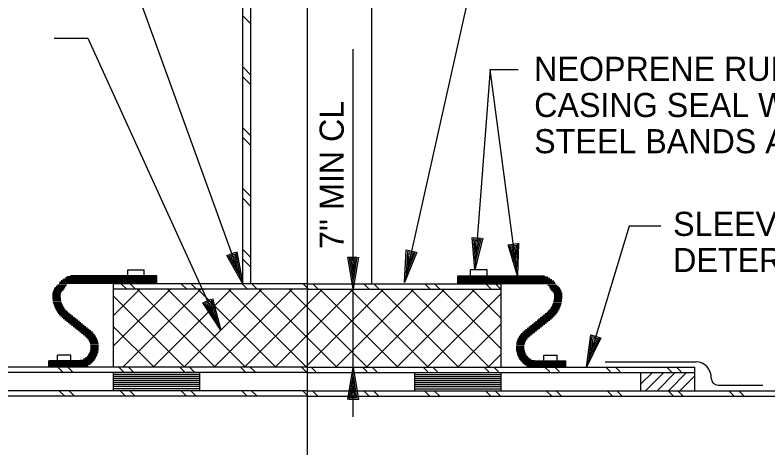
# Model space of a CAD drawing. Extents: x 22422.9 to 22498.9, y 22369.6 to 22415.
# Drawn here: x 22465.87 to 22471.7, y 22388.07 to 22391.43 of the extents above; entities that cross this region are included whole.
import ezdxf

# ---------------------------------------------------------------- set-up
doc = ezdxf.new("R2010")
doc.units = 0
for name, color, linetype in [('Level 1', 7, 'Continuous'), ('Level 2', 7, 'Continuous'), ('Level 4', 7, 'Continuous'), ('Level 7', 7, 'Continuous'), ('Level 8', 7, 'Continuous')]:
    doc.layers.add(name, color=color, linetype=linetype)

msp = doc.modelspace()

# ---------------------------------------------------------------- linework, layer by layer
at = {"layer": 'Level 1'}
for p, q in [((22468.1298, 22384.5979), (22468.1298, 22394.0328)), ((22468.4836, 22389.3005), (22468.4836, 22391.1625)), ((22469.7308, 22389.6069), (22469.7308, 22389.6069)), ((22467.6062, 22389.5324), (22467.6062, 22389.5324)), ((22469.7393, 22389.5424), (22469.7393, 22389.5424)), ((22469.7399, 22389.5381), (22469.7399, 22389.5381)), ((22469.7399, 22389.5381), (22469.7399, 22389.5381)), ((22466.7386, 22389.4038), (22466.7386, 22389.4515)), ((22466.7386, 22389.4515), (22466.866, 22389.4515)), ((22466.866, 22389.4038), (22466.866, 22389.4515)), ((22467.6298, 22389.4672), (22467.6298, 22389.4672)), ((22469.3936, 22389.4038), (22469.3936, 22389.4515)), ((22469.521, 22389.4515), (22469.3936, 22389.4515)), ((22469.521, 22389.4038), (22469.521, 22389.4515)), ((22466.6298, 22388.6963), (22466.6298, 22389.3422)), ((22468.1298, 22389.3422), (22466.6298, 22389.3422)), ((22468.1298, 22389.3422), (22469.6298, 22389.3422)), ((22469.6298, 22388.6963), (22469.6298, 22389.3422)), ((22468.1298, 22389.3005), (22466.6298, 22389.3005)), ((22468.1298, 22389.3005), (22469.6298, 22389.3005)), ((22468.4836, 22388.6963), (22468.4836, 22389.3005)), ((22466.999, 22389.0152), (22466.999, 22389.0152)), ((22467.0402, 22388.9594), (22467.0402, 22388.9594)), ((22468.5915, 22388.8065), (22468.5915, 22388.8065)), ((22466.1946, 22388.746), (22466.1946, 22388.789)), ((22466.2982, 22388.789), (22466.1946, 22388.789)), ((22466.2982, 22388.746), (22466.2982, 22388.789)), ((22469.9614, 22388.746), (22469.9614, 22388.789)), ((22469.9614, 22388.789), (22470.065, 22388.789)), ((22470.065, 22388.746), (22470.065, 22388.789)), ((22468.1298, 22388.6963), (22465.1298, 22388.6963)), ((22468.1298, 22388.6963), (22471.1298, 22388.6963)), ((22468.4836, 22388.3111), (22468.4836, 22388.6963)), ((22468.581, 22388.738), (22468.581, 22388.738)), ((22468.1298, 22388.6547), (22465.1298, 22388.6547)), ((22467.2965, 22388.639), (22466.6298, 22388.639)), ((22468.1298, 22388.6547), (22471.1298, 22388.6547)), ((22468.9631, 22388.639), (22469.6298, 22388.639)), ((22470.7131, 22388.5663), (22470.8015, 22388.6547)), ((22470.7493, 22388.514), (22470.8899, 22388.6547)), ((22470.8377, 22388.514), (22470.9783, 22388.6547)), ((22470.9261, 22388.514), (22471.0667, 22388.6547)), ((22471.0145, 22388.514), (22471.1298, 22388.6294)), ((22467.2965, 22388.6234), (22466.6298, 22388.6234)), ((22467.2965, 22388.6078), (22466.6298, 22388.6078)), ((22467.2965, 22388.5922), (22466.6298, 22388.5922)), ((22467.2965, 22388.5765), (22466.6298, 22388.5765)), ((22468.9631, 22388.6234), (22469.6298, 22388.6234)), ((22468.9631, 22388.6078), (22469.6298, 22388.6078)), ((22468.9631, 22388.5922), (22469.6298, 22388.5922)), ((22468.9631, 22388.5765), (22469.6298, 22388.5765)), ((22467.2965, 22388.5609), (22466.6298, 22388.5609)), ((22467.2965, 22388.5453), (22466.6298, 22388.5453)), ((22467.2965, 22388.5297), (22466.6298, 22388.5297)), ((22468.9631, 22388.5609), (22469.6298, 22388.5609)), ((22468.9631, 22388.5453), (22469.6298, 22388.5453)), ((22468.9631, 22388.5297), (22469.6298, 22388.5297))]:
    msp.add_line(p, q, dxfattribs=at)
msp.add_lwpolyline([(22469.7404, 22389.5539), (22469.7399, 22389.5381), (22469.7353, 22389.5532), (22469.7397, 22389.5538), (22469.7393, 22389.5424), (22469.7362, 22389.5527), (22469.739, 22389.5531), (22469.7388, 22389.5466), (22469.7371, 22389.5521), (22469.7383, 22389.5523), (22469.7382, 22389.5508)], dxfattribs=at)
at = {"layer": 'Level 2'}
for p, q in [((22467.6298, 22389.3422), (22467.6298, 22393.2738)), ((22467.6923, 22389.3422), (22467.6923, 22393.2738)), ((22468.6298, 22389.3422), (22468.6298, 22393.2738)), ((22467.6298, 22389.3422), (22466.68, 22391.9696)), ((22469.7577, 22389.4038), (22469.5456, 22391.0035)), ((22469.5456, 22391.0035), (22469.7633, 22391.0035)), ((22466.9643, 22389.4038), (22466.2958, 22389.4038)), ((22466.9643, 22389.3422), (22466.9643, 22389.4038)), ((22469.2953, 22389.4038), (22469.9648, 22389.4038)), ((22469.2953, 22389.3422), (22469.2953, 22389.4038)), ((22466.3909, 22388.746), (22466.1285, 22388.746)), ((22466.1285, 22388.6963), (22466.1285, 22388.746)), ((22469.8687, 22388.746), (22470.1311, 22388.746)), ((22470.1311, 22388.6963), (22470.1311, 22388.746)), ((22471.1298, 22388.514), (22471.1298, 22388.6963)), ((22466.6298, 22388.514), (22466.6298, 22388.6547)), ((22467.2965, 22388.514), (22467.2965, 22388.6547)), ((22468.9631, 22388.514), (22468.9631, 22388.6547)), ((22469.6298, 22388.514), (22469.6298, 22388.6547)), ((22470.7131, 22388.514), (22470.7131, 22388.6547)), ((22468.1298, 22388.514), (22461.4631, 22388.514)), ((22468.1298, 22388.514), (22474.774, 22388.514)), ((22468.1298, 22388.4724), (22461.4924, 22388.4724)), ((22468.1298, 22388.4724), (22474.7645, 22388.4724))]:
    msp.add_line(p, q, dxfattribs=at)
for points in [[(22469.7546, 22391.9303), (22469.458, 22391.9303), (22468.8819, 22389.353)], [(22466.1686, 22391.2463), (22466.4291, 22391.2463), (22467.4606, 22388.9844)], [(22469.5456, 22391.0035), (22469.4274, 22389.4506)], [(22470.867, 22389.79), (22470.6212, 22389.79), (22470.2916, 22388.6963)], [(22469.4875, 22389.6961), (22469.4274, 22389.4506), (22469.4051, 22389.7024), (22469.4756, 22389.697), (22469.4327, 22389.5197), (22469.4176, 22389.6907), (22469.4628, 22389.6873), (22469.4377, 22389.5862), (22469.4301, 22389.6791), (22469.4487, 22389.6776), (22469.443, 22389.6553)], [(22469.7659, 22389.6564), (22469.7577, 22389.4038), (22469.684, 22389.6455), (22469.754, 22389.6548), (22469.7486, 22389.4725), (22469.6986, 22389.6367), (22469.7435, 22389.6427), (22469.7398, 22389.5386), (22469.7132, 22389.6279), (22469.7317, 22389.6304), (22469.7307, 22389.6074)], [(22467.5839, 22389.5907), (22467.6298, 22389.3422), (22467.5062, 22389.5626), (22467.5726, 22389.5866), (22467.6062, 22389.4074), (22467.5223, 22389.5571), (22467.565, 22389.5725), (22467.5836, 22389.4701), (22467.5385, 22389.5516), (22467.5561, 22389.5579), (22467.56, 22389.5353)], [(22468.9766, 22389.5873), (22468.8819, 22389.353), (22468.8959, 22389.6053), (22468.9649, 22389.5899), (22468.897, 22389.4207), (22468.9066, 22389.592), (22468.9508, 22389.5821), (22468.9115, 22389.4857), (22468.9173, 22389.5787), (22468.9355, 22389.5746), (22468.9267, 22389.5534)], [(22468.5249, 22389.5498), (22468.4836, 22389.3005), (22468.4422, 22389.5498), (22468.5129, 22389.5498), (22468.4836, 22389.3698), (22468.4556, 22389.5392), (22468.5009, 22389.5392), (22468.4836, 22389.4365), (22468.4689, 22389.5285), (22468.4876, 22389.5285), (22468.4836, 22389.5058)], [(22466.9631, 22389.3964), (22466.2686, 22389.3964)], [(22469.2965, 22389.3964), (22469.991, 22389.3964)], [(22466.2672, 22389.3317), (22466.195, 22389.3317)], [(22466.9631, 22389.3444), (22466.2073, 22389.3444)], [(22466.9631, 22389.3548), (22466.2137, 22389.3548)], [(22466.9631, 22389.3652), (22466.2223, 22389.3652)], [(22466.9631, 22389.3756), (22466.2375, 22389.3756)], [(22466.9631, 22389.386), (22466.2533, 22389.386)], [(22469.2965, 22389.386), (22470.0063, 22389.386)], [(22469.2965, 22389.3756), (22470.0221, 22389.3756)], [(22469.2965, 22389.3652), (22470.0373, 22389.3652)], [(22469.2965, 22389.3548), (22470.0459, 22389.3548)], [(22469.2965, 22389.3444), (22470.0524, 22389.3444)], [(22469.9924, 22389.3317), (22470.0646, 22389.3317)], [(22466.2292, 22389.2797), (22466.1608, 22389.2797)], [(22466.2389, 22389.2901), (22466.1634, 22389.2901)], [(22466.246, 22389.3005), (22466.1692, 22389.3005)], [(22466.2524, 22389.3109), (22466.1757, 22389.3109)], [(22466.2582, 22389.3213), (22466.1847, 22389.3213)], [(22470.0014, 22389.3213), (22470.0749, 22389.3213)], [(22470.0072, 22389.3109), (22470.084, 22389.3109)], [(22470.0137, 22389.3005), (22470.0904, 22389.3005)], [(22470.0207, 22389.2901), (22470.0962, 22389.2901)], [(22470.0304, 22389.2797), (22470.0988, 22389.2797)], [(22466.2185, 22389.2484), (22466.156, 22389.2484)], [(22466.2189, 22389.2588), (22466.1563, 22389.2588)], [(22466.2189, 22389.238), (22466.1563, 22389.238)], [(22466.222, 22389.2692), (22466.157, 22389.2692)], [(22466.2199, 22389.2276), (22466.157, 22389.2276)], [(22466.2215, 22389.2172), (22466.1582, 22389.2172)], [(22467.3947, 22389.2284), (22467.4606, 22388.9844), (22467.3195, 22389.1941), (22467.3838, 22389.2235), (22467.4318, 22389.0475), (22467.3361, 22389.19), (22467.3773, 22389.2088), (22467.4042, 22389.1082), (22467.3527, 22389.1858), (22467.3696, 22389.1935), (22467.3754, 22389.1713)], [(22470.0376, 22389.2692), (22470.1026, 22389.2692)], [(22470.0381, 22389.2172), (22470.1014, 22389.2172)], [(22470.0398, 22389.2276), (22470.1026, 22389.2276)], [(22470.0407, 22389.2588), (22470.1033, 22389.2588)], [(22470.0407, 22389.238), (22470.1033, 22389.238)], [(22470.0411, 22389.2484), (22470.1036, 22389.2484)], [(22466.2239, 22389.2067), (22466.1599, 22389.2067)], [(22466.2269, 22389.1963), (22466.1621, 22389.1963)], [(22466.2307, 22389.1859), (22466.1648, 22389.1859)], [(22466.2354, 22389.1755), (22466.168, 22389.1755)], [(22466.2409, 22389.1651), (22466.1718, 22389.1651)], [(22466.2475, 22389.1547), (22466.1761, 22389.1547)], [(22470.0121, 22389.1547), (22470.0835, 22389.1547)], [(22470.0187, 22389.1651), (22470.0878, 22389.1651)], [(22470.0242, 22389.1755), (22470.0916, 22389.1755)], [(22470.0289, 22389.1859), (22470.0949, 22389.1859)], [(22470.0327, 22389.1963), (22470.0975, 22389.1963)], [(22470.0357, 22389.2067), (22470.0997, 22389.2067)], [(22466.2552, 22389.1442), (22466.1811, 22389.1442)], [(22466.2643, 22389.1338), (22466.1868, 22389.1338)], [(22466.2751, 22389.1234), (22466.1932, 22389.1234)], [(22466.2877, 22389.113), (22466.2004, 22389.113)], [(22466.3004, 22389.1026), (22466.2085, 22389.1026)], [(22469.9592, 22389.1026), (22470.0511, 22389.1026)], [(22469.972, 22389.113), (22470.0592, 22389.113)], [(22469.9845, 22389.1234), (22470.0664, 22389.1234)], [(22469.9953, 22389.1338), (22470.0728, 22389.1338)], [(22470.0044, 22389.1442), (22470.0785, 22389.1442)], [(22466.3132, 22389.0922), (22466.2176, 22389.0922)], [(22466.3259, 22389.0817), (22466.228, 22389.0817)], [(22466.3387, 22389.0713), (22466.2399, 22389.0713)], [(22466.3515, 22389.0609), (22466.2526, 22389.0609)], [(22466.3642, 22389.0505), (22466.2654, 22389.0505)], [(22466.377, 22389.0401), (22466.2782, 22389.0401)], [(22469.8826, 22389.0401), (22469.9815, 22389.0401)], [(22469.8954, 22389.0505), (22469.9942, 22389.0505)], [(22469.9081, 22389.0609), (22470.007, 22389.0609)], [(22469.9209, 22389.0713), (22470.0197, 22389.0713)], [(22469.9337, 22389.0817), (22470.0316, 22389.0817)], [(22469.9464, 22389.0922), (22470.042, 22389.0922)], [(22466.3898, 22389.0297), (22466.2909, 22389.0297)], [(22466.4025, 22389.0192), (22466.3037, 22389.0192)], [(22466.4153, 22389.0088), (22466.3165, 22389.0088)], [(22466.4281, 22388.9984), (22466.3292, 22388.9984)], [(22466.4408, 22388.988), (22466.342, 22388.988)], [(22469.8188, 22388.988), (22469.9176, 22388.988)], [(22469.8315, 22388.9984), (22469.9304, 22388.9984)], [(22469.8443, 22389.0088), (22469.9432, 22389.0088)], [(22469.8571, 22389.0192), (22469.9559, 22389.0192)], [(22469.8698, 22389.0297), (22469.9687, 22389.0297)], [(22466.4536, 22388.9776), (22466.3548, 22388.9776)], [(22466.4649, 22388.9672), (22466.3675, 22388.9672)], [(22466.4744, 22388.9567), (22466.3803, 22388.9567)], [(22466.4825, 22388.9463), (22466.393, 22388.9463)], [(22466.4893, 22388.9359), (22466.4058, 22388.9359)], [(22466.4951, 22388.9255), (22466.4182, 22388.9255)], [(22469.7645, 22388.9255), (22469.8414, 22388.9255)], [(22469.7703, 22388.9359), (22469.8538, 22388.9359)], [(22469.7772, 22388.9463), (22469.8666, 22388.9463)], [(22469.7852, 22388.9567), (22469.8793, 22388.9567)], [(22469.7947, 22388.9672), (22469.8921, 22388.9672)], [(22469.806, 22388.9776), (22469.9049, 22388.9776)], [(22470.4031, 22388.9231), (22470.2916, 22388.6963), (22470.3239, 22388.947), (22470.3916, 22388.9266), (22470.3116, 22388.7627), (22470.3336, 22388.9329), (22470.377, 22388.9198), (22470.3308, 22388.8265), (22470.3433, 22388.9189), (22470.3612, 22388.9135), (22470.3508, 22388.8929)], [(22466.5, 22388.9151), (22466.4278, 22388.9151)], [(22466.504, 22388.9047), (22466.4352, 22388.9047)], [(22466.5072, 22388.8942), (22466.4408, 22388.8942)], [(22466.5098, 22388.8838), (22466.4451, 22388.8838)], [(22466.5116, 22388.8734), (22466.4481, 22388.8734)], [(22466.5128, 22388.863), (22466.45, 22388.863)], [(22469.7468, 22388.863), (22469.8096, 22388.863)], [(22469.748, 22388.8734), (22469.8115, 22388.8734)], [(22469.7498, 22388.8838), (22469.8145, 22388.8838)], [(22469.7524, 22388.8942), (22469.8188, 22388.8942)], [(22469.7556, 22388.9047), (22469.8244, 22388.9047)], [(22469.7597, 22388.9151), (22469.8318, 22388.9151)], [(22466.5087, 22388.8109), (22466.4433, 22388.8109)], [(22466.5108, 22388.8213), (22466.4469, 22388.8213)], [(22466.5123, 22388.8317), (22466.4493, 22388.8317)], [(22466.5131, 22388.8422), (22466.4505, 22388.8422)], [(22466.5133, 22388.8526), (22466.4508, 22388.8526)], [(22469.7463, 22388.8526), (22469.8088, 22388.8526)], [(22469.7465, 22388.8422), (22469.8091, 22388.8422)], [(22469.7473, 22388.8317), (22469.8104, 22388.8317)], [(22469.7488, 22388.8213), (22469.8127, 22388.8213)], [(22469.7509, 22388.8109), (22469.8163, 22388.8109)], [(22466.4789, 22388.7484), (22466.3708, 22388.7484)], [(22466.4863, 22388.7588), (22466.3975, 22388.7588)], [(22466.4926, 22388.7692), (22466.4128, 22388.7692)], [(22466.4978, 22388.7797), (22466.4237, 22388.7797)], [(22466.5023, 22388.7901), (22466.432, 22388.7901)], [(22466.5058, 22388.8005), (22466.4384, 22388.8005)], [(22469.7538, 22388.8005), (22469.8212, 22388.8005)], [(22469.7574, 22388.7901), (22469.8276, 22388.7901)], [(22469.7618, 22388.7797), (22469.8359, 22388.7797)], [(22469.7671, 22388.7692), (22469.8468, 22388.7692)], [(22469.7733, 22388.7588), (22469.8621, 22388.7588)], [(22469.7807, 22388.7484), (22469.8888, 22388.7484)], [(22466.4703, 22388.738), (22466.1298, 22388.738)], [(22466.46, 22388.7276), (22466.1298, 22388.7276)], [(22466.4476, 22388.7172), (22466.1298, 22388.7172)], [(22466.4323, 22388.7067), (22466.1298, 22388.7067)], [(22466.4118, 22388.6963), (22466.1298, 22388.6963)], [(22468.4422, 22388.447), (22468.4836, 22388.6963), (22468.5249, 22388.447), (22468.4542, 22388.447), (22468.4836, 22388.627), (22468.5116, 22388.4577), (22468.4662, 22388.4577), (22468.4836, 22388.5603), (22468.4982, 22388.4683), (22468.4796, 22388.4683), (22468.4836, 22388.491)], [(22469.7893, 22388.738), (22470.1298, 22388.738)], [(22469.7996, 22388.7276), (22470.1298, 22388.7276)], [(22469.812, 22388.7172), (22470.1298, 22388.7172)], [(22469.8274, 22388.7067), (22470.1298, 22388.7067)], [(22469.8478, 22388.6963), (22470.1298, 22388.6963)]]:
    msp.add_lwpolyline(points, dxfattribs=at)
at = {"layer": 'Level 7'}
for p, q in [((22470.4365, 22388.738), (22471.1402, 22388.738)), ((22471.3103, 22388.5557), (22471.6575, 22388.5557))]:
    msp.add_line(p, q, dxfattribs=at)
for centre, radius, start, end in [((22471.135, 22388.6156), 0.1225, 357.56335, 87.56335), ((22471.3103, 22388.6104), 0.0529, 180, 270)]:
    msp.add_arc(centre, radius, start, end, dxfattribs=at)
at = {"layer": 'Level 8'}
for p, q in [((22469.4327, 22389.5197), (22469.4327, 22389.5197)), ((22469.4274, 22389.4506), (22469.4274, 22389.4506)), ((22468.897, 22389.4207), (22468.897, 22389.4207)), ((22468.4836, 22389.3698), (22468.4836, 22389.3698)), ((22468.8819, 22389.353), (22468.8819, 22389.353)), ((22468.4836, 22389.3005), (22468.4836, 22389.3005)), ((22467.4318, 22389.0475), (22467.4318, 22389.0475)), ((22467.4606, 22388.9844), (22467.4606, 22388.9844)), ((22470.3116, 22388.7627), (22470.3116, 22388.7627)), ((22468.4836, 22388.6963), (22468.4836, 22388.6963)), ((22470.2916, 22388.6963), (22470.2916, 22388.6963)), ((22468.4836, 22388.627), (22468.4836, 22388.627))]:
    msp.add_line(p, q, dxfattribs=at)
for points in [[(22467.6923, 22391.3567), (22467.6298, 22391.4193)], [(22467.6923, 22390.9608), (22467.6298, 22391.0233)], [(22467.6923, 22390.8853), (22467.6298, 22390.9479)], [(22467.6923, 22390.4894), (22467.6298, 22390.5519)], [(22467.6923, 22390.4139), (22467.6298, 22390.4765)], [(22467.6923, 22390.018), (22467.6298, 22390.0805)], [(22467.6923, 22389.9425), (22467.6298, 22390.0051)], [(22467.6923, 22389.5466), (22467.6298, 22389.6091)], [(22467.6923, 22389.4711), (22467.6298, 22389.5336)], [(22466.7308, 22389.3005), (22466.6892, 22389.3422)], [(22466.7993, 22389.3005), (22466.7577, 22389.3422)], [(22467.1953, 22389.3005), (22467.1536, 22389.3422)], [(22467.2707, 22389.3005), (22467.2291, 22389.3422)], [(22467.6667, 22389.3005), (22467.625, 22389.3422)], [(22467.7422, 22389.3005), (22467.7005, 22389.3422)], [(22468.1381, 22389.3005), (22468.0965, 22389.3422)], [(22468.2135, 22389.3005), (22468.1719, 22389.3422)], [(22468.6095, 22389.3005), (22468.5679, 22389.3422)], [(22468.685, 22389.3005), (22468.6433, 22389.3422)], [(22469.0809, 22389.3005), (22469.0392, 22389.3422)], [(22469.1563, 22389.3005), (22469.1147, 22389.3422)], [(22469.5523, 22389.3005), (22469.5107, 22389.3422)], [(22469.6277, 22389.3005), (22469.5861, 22389.3422)], [(22466.6298, 22388.8607), (22467.0695, 22389.3005)], [(22466.6298, 22389.0964), (22466.8338, 22389.3005)], [(22466.7011, 22388.6963), (22467.3053, 22389.3005)], [(22467.4152, 22388.6963), (22466.811, 22389.3005)], [(22466.9368, 22388.6963), (22467.541, 22389.3005)], [(22467.6509, 22388.6963), (22467.0467, 22389.3005)], [(22467.1725, 22388.6963), (22467.7767, 22389.3005)], [(22467.8866, 22388.6963), (22467.2824, 22389.3005)], [(22467.4082, 22388.6963), (22468.0124, 22389.3005)], [(22468.1223, 22388.6963), (22467.5181, 22389.3005)], [(22467.6439, 22388.6963), (22468.2481, 22389.3005)], [(22468.358, 22388.6963), (22467.7538, 22389.3005)], [(22467.8796, 22388.6963), (22468.4838, 22389.3005)], [(22468.5937, 22388.6963), (22467.9895, 22389.3005)], [(22468.1153, 22388.6963), (22468.7195, 22389.3005)], [(22468.8294, 22388.6963), (22468.2252, 22389.3005)], [(22468.351, 22388.6963), (22468.9552, 22389.3005)], [(22469.0651, 22388.6963), (22468.4609, 22389.3005)], [(22468.5867, 22388.6963), (22469.1909, 22389.3005)], [(22469.3008, 22388.6963), (22468.6966, 22389.3005)], [(22468.8224, 22388.6963), (22469.4266, 22389.3005)], [(22469.5365, 22388.6963), (22468.9323, 22389.3005)], [(22469.6298, 22388.8387), (22469.168, 22389.3005)], [(22469.6298, 22389.0744), (22469.4037, 22389.3005)], [(22467.1795, 22388.6963), (22466.6298, 22389.246)], [(22469.0581, 22388.6963), (22469.6298, 22389.268)], [(22466.9438, 22388.6963), (22466.6298, 22389.0103)], [(22469.2938, 22388.6963), (22469.6298, 22389.0323)], [(22469.5295, 22388.6963), (22469.6298, 22388.7966)], [(22466.2349, 22388.6599), (22466.1985, 22388.6963)], [(22466.3104, 22388.6599), (22466.2739, 22388.6963)], [(22466.7063, 22388.6599), (22466.6699, 22388.6963)], [(22466.7818, 22388.6599), (22466.7453, 22388.6963)], [(22467.1778, 22388.6599), (22467.1413, 22388.6963)], [(22467.2532, 22388.6599), (22467.2167, 22388.6963)], [(22467.6492, 22388.6599), (22467.6127, 22388.6963)], [(22467.7246, 22388.6599), (22467.6881, 22388.6963)], [(22468.1206, 22388.6599), (22468.0841, 22388.6963)], [(22468.196, 22388.6599), (22468.1595, 22388.6963)], [(22468.592, 22388.6599), (22468.5555, 22388.6963)], [(22468.6674, 22388.6599), (22468.6309, 22388.6963)], [(22469.0634, 22388.6599), (22469.0269, 22388.6963)], [(22469.1388, 22388.6599), (22469.1023, 22388.6963)], [(22469.5348, 22388.6599), (22469.4983, 22388.6963)], [(22469.6102, 22388.6599), (22469.5737, 22388.6963)], [(22470.0062, 22388.6599), (22469.9697, 22388.6963)], [(22470.0816, 22388.6599), (22470.0451, 22388.6963)], [(22470.4776, 22388.6599), (22470.4411, 22388.6963)], [(22470.553, 22388.6599), (22470.5165, 22388.6963)], [(22470.949, 22388.6599), (22470.9125, 22388.6963)], [(22471.0244, 22388.6599), (22470.988, 22388.6963)], [(22466.2506, 22388.4724), (22466.2089, 22388.514)], [(22466.326, 22388.4724), (22466.2843, 22388.514)], [(22466.722, 22388.4724), (22466.6803, 22388.514)], [(22466.7974, 22388.4724), (22466.7557, 22388.514)], [(22467.1934, 22388.4724), (22467.1517, 22388.514)], [(22467.2688, 22388.4724), (22467.2271, 22388.514)], [(22467.6648, 22388.4724), (22467.6231, 22388.514)], [(22467.7402, 22388.4724), (22467.6985, 22388.514)], [(22468.1362, 22388.4724), (22468.0945, 22388.514)], [(22468.2116, 22388.4724), (22468.1699, 22388.514)], [(22468.6076, 22388.4724), (22468.5659, 22388.514)], [(22468.683, 22388.4724), (22468.6413, 22388.514)], [(22469.079, 22388.4724), (22469.0373, 22388.514)], [(22469.1544, 22388.4724), (22469.1128, 22388.514)], [(22469.5504, 22388.4724), (22469.5087, 22388.514)], [(22469.6258, 22388.4724), (22469.5842, 22388.514)], [(22470.0218, 22388.4724), (22469.9801, 22388.514)], [(22470.0972, 22388.4724), (22470.0556, 22388.514)], [(22470.4932, 22388.4724), (22470.4515, 22388.514)], [(22470.5686, 22388.4724), (22470.527, 22388.514)], [(22470.9646, 22388.4724), (22470.9229, 22388.514)], [(22471.04, 22388.4724), (22470.9984, 22388.514)], [(22471.436, 22388.4724), (22471.3943, 22388.514)], [(22471.5114, 22388.4724), (22471.4698, 22388.514)]]:
    msp.add_lwpolyline(points, dxfattribs=at)

# ---------------------------------------------------------------- texts
at = {"layer": 'Level 4'}
for s, p in [('NEOPRENE RUBBER SLEEVE TYPE', (22469.8861, 22390.9156)), ('CASING SEAL WITH STAINLESS', (22469.8861, 22390.6351)), ('STEEL BANDS AND CLAMPS', (22469.8861, 22390.3547)), ('SLEEVE, STEEL PIPE SIZE', (22470.9621, 22389.7138)), ('DETERMINED BY LINK-SEAL', (22470.9621, 22389.4334))]:
    msp.add_text(s, height=0.186667, dxfattribs=at).set_placement(p)
msp.add_text("7'' MIN CL ", height=0.186667, rotation=90, dxfattribs=at).set_placement((22468.4113, 22389.6117))

doc.saveas('drawing.dxf')
